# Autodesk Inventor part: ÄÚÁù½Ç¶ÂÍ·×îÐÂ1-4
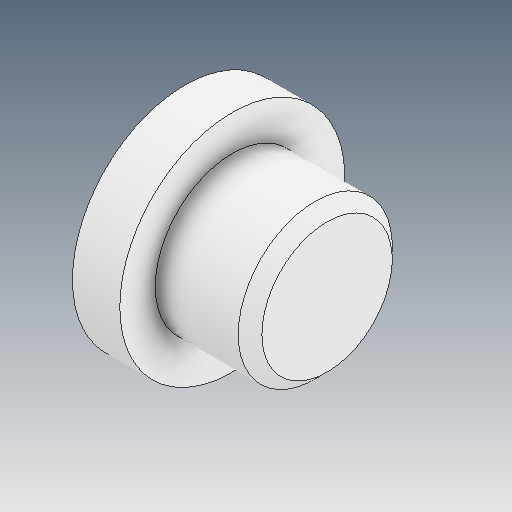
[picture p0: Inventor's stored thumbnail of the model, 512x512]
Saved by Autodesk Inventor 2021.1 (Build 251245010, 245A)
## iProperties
Created: 2021-05
Part Number: ÄÚÁù½Ç¶ÂÍ·×îÐÂ1-4
Material: Ogólny
Document SubType Name: Modeling
Designer: user
Density: 1 g/cm^3
Appearance: Domyślna
Author: user
Revision Number: ÈÎºÎ
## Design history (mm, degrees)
feature "ÊäÈë1"
node "Bryła1"
